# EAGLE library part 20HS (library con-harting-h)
CONNECTOR
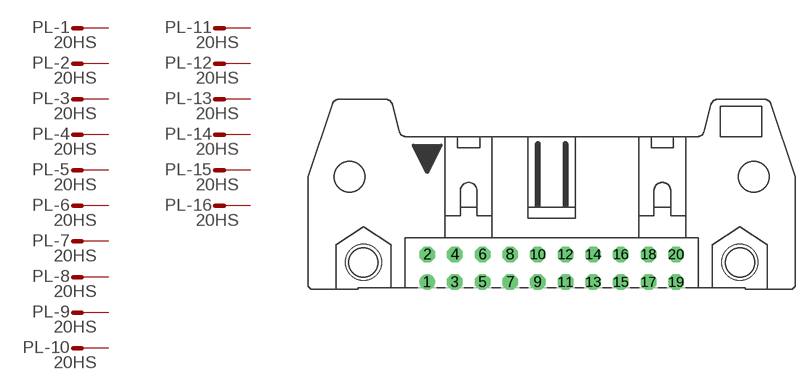
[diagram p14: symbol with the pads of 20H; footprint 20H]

Designator prefix PL; gates -1=M -2=M -3=M -4=M -5=M -6=M -7=M -8=M -9=M -10=M -11=M -12=M -13=M -14=M -15=M -16=M -17=M -18=M -19=M -20=M

## 20HS (OC_FARNELL: unknown; OC_NEWARK: unknown)  [20H]
1  -1:S  pas
2  -2:S  pas
3  -3:S  pas
4  -4:S  pas
5  -5:S  pas
6  -6:S  pas
7  -7:S  pas
8  -8:S  pas
9  -9:S  pas
10  -10:S  pas
11  -11:S  pas
12  -12:S  pas
13  -13:S  pas
14  -14:S  pas
15  -15:S  pas
16  -16:S  pas
17  -17:S  pas
18  -18:S  pas
19  -19:S  pas
20  -20:S  pas

## Footprint 20H (pad centres in mm)
CONNECTOR
drill 0.914 round: 1 -11.43,-1.27
drill 0.914 octagon: 2 -11.43,1.27; 3 -8.89,-1.27; 4 -8.89,1.27; 5 -6.35,-1.27; 6 -6.35,1.27; 7 -3.81,-1.27; 8 -3.81,1.27; 9 -1.27,-1.27; 10 -1.27,1.27; 11 1.27,-1.27; 12 1.27,1.27; 13 3.81,-1.27; 14 3.81,1.27; 15 6.35,-1.27; 16 6.35,1.27; 17 8.89,-1.27; 18 8.89,1.27; 19 11.43,-1.27; 20 11.43,1.27
hole 3.302 at -17.272,0.533
hole 3.302 at 17.272,0.533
